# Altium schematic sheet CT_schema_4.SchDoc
size 469 x 430 mm
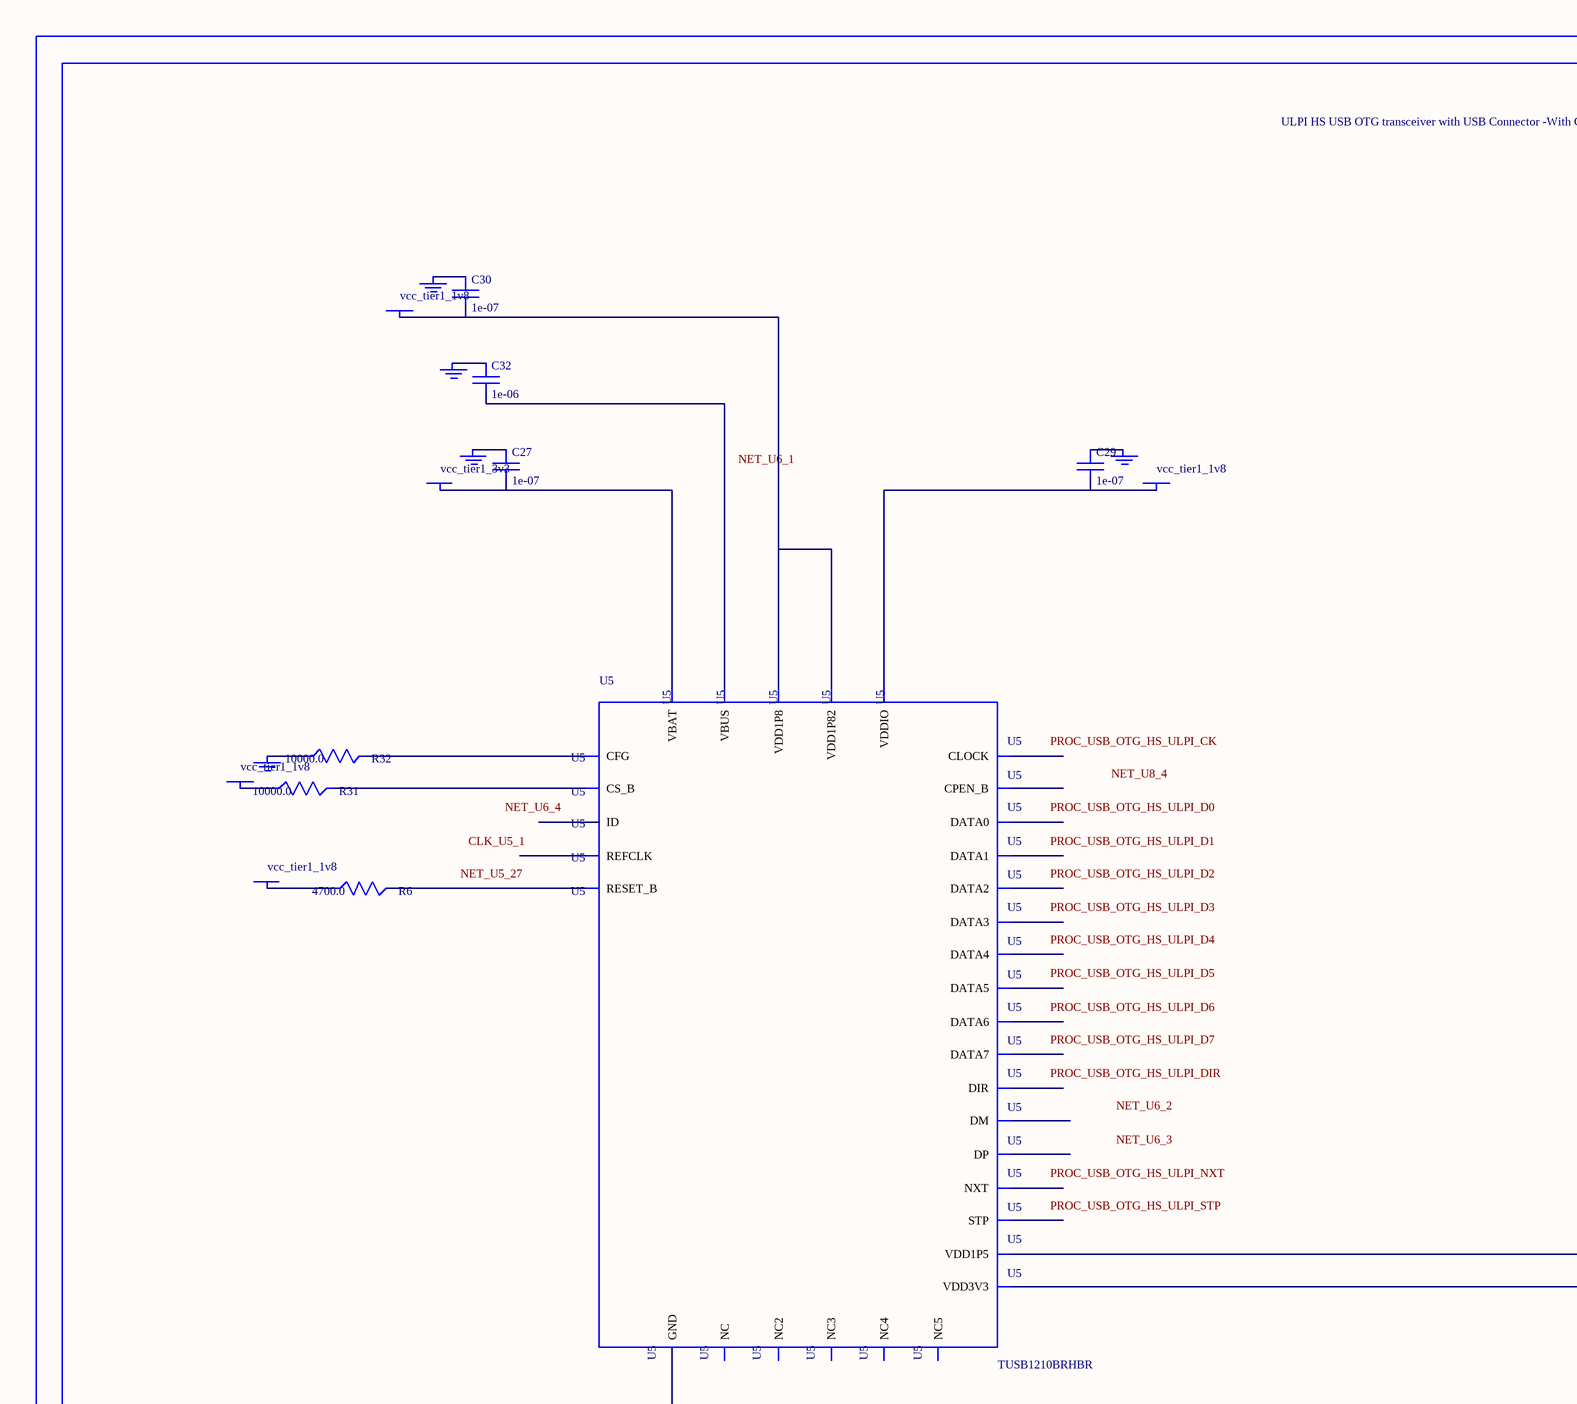
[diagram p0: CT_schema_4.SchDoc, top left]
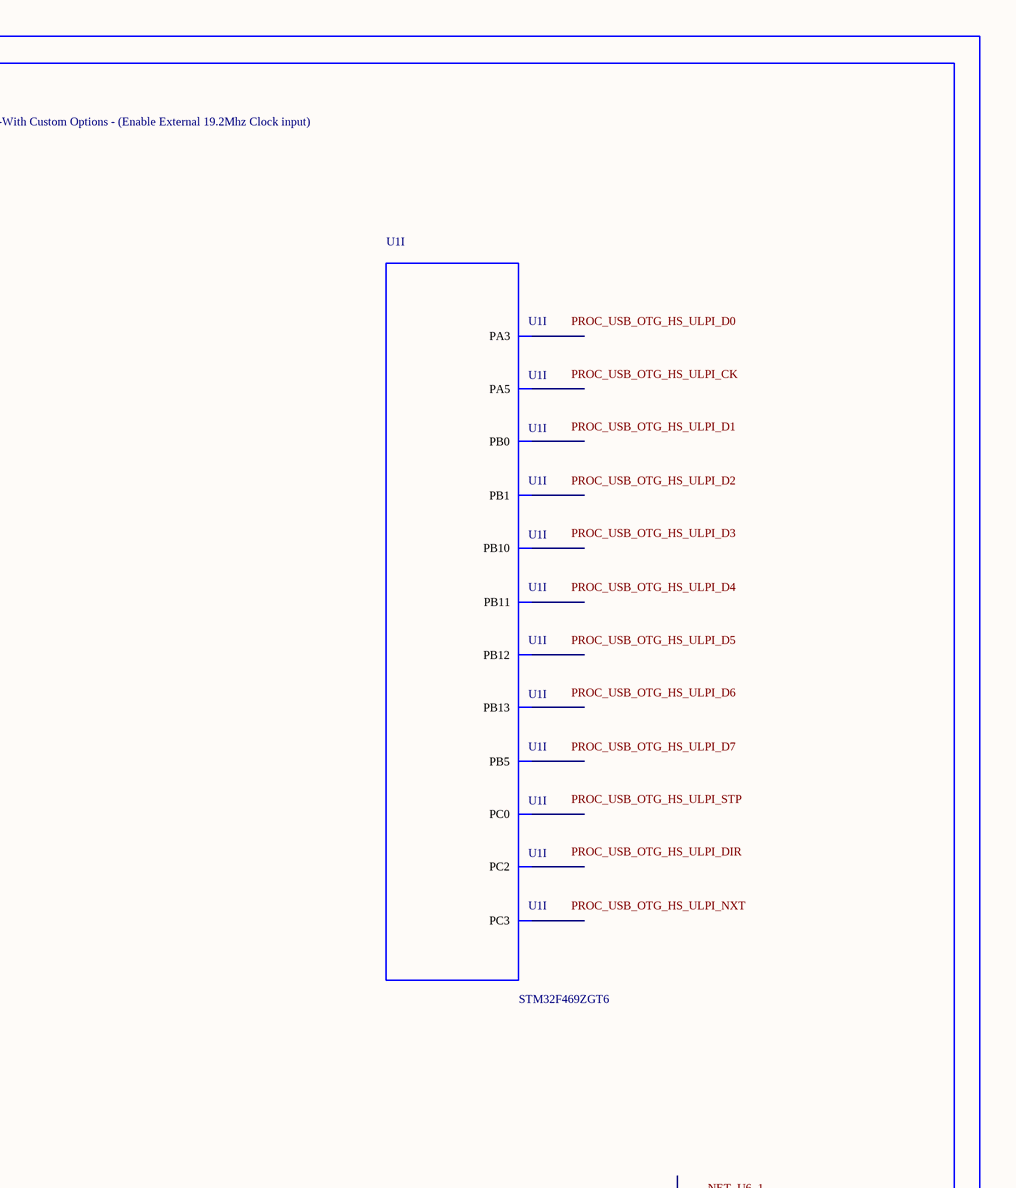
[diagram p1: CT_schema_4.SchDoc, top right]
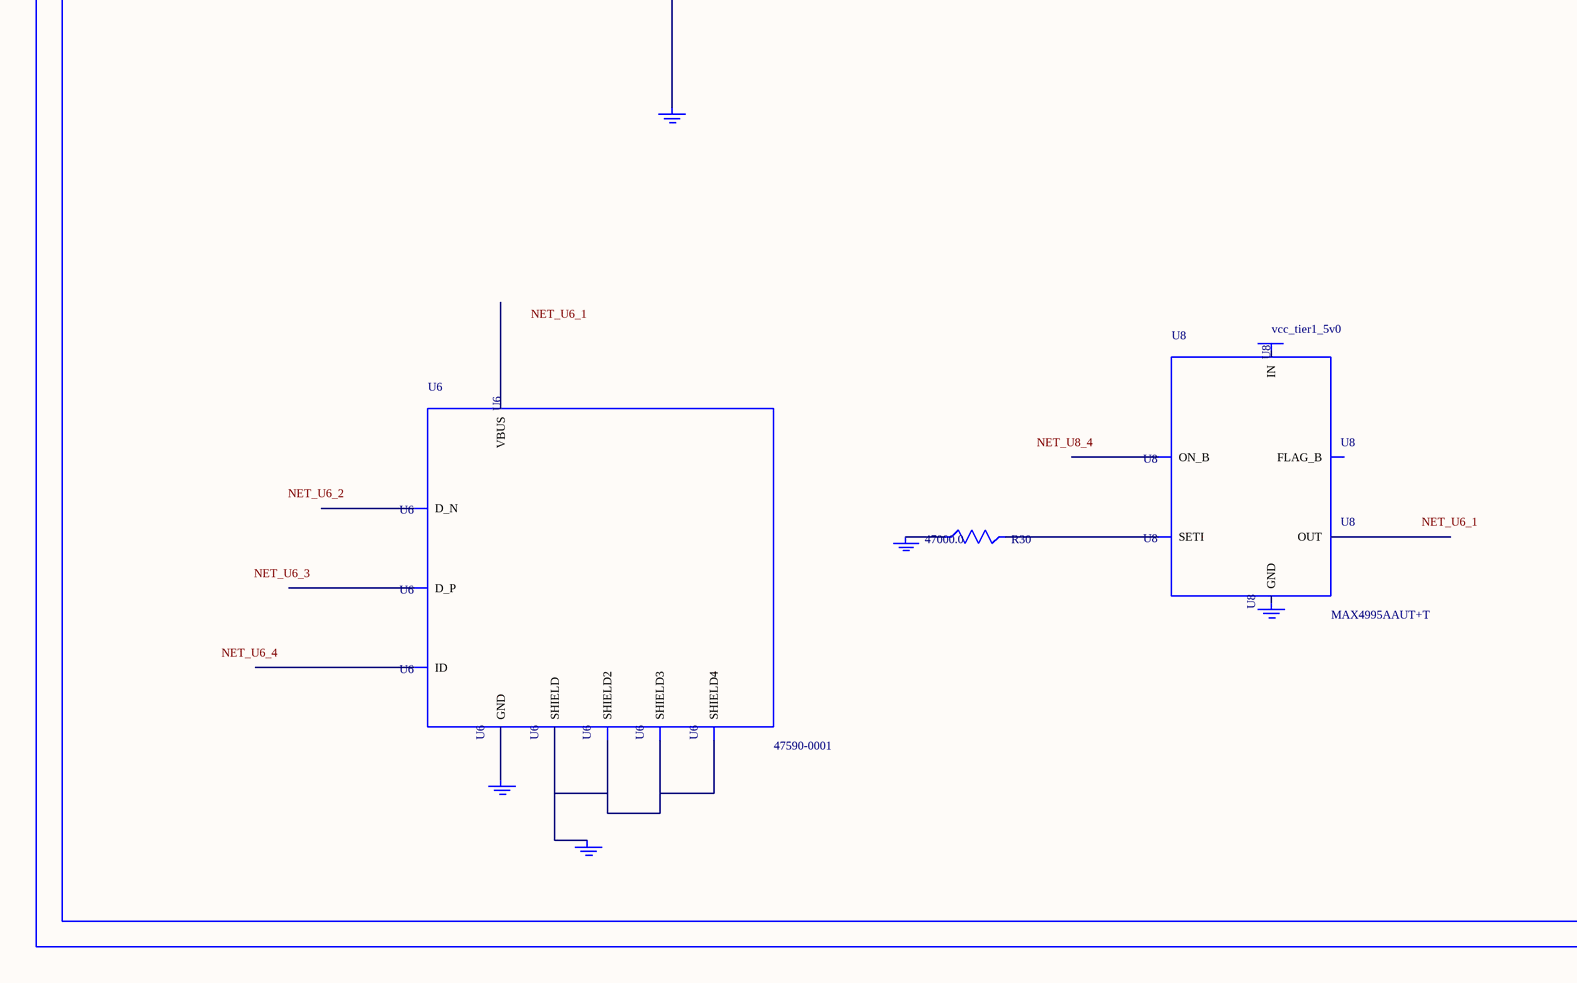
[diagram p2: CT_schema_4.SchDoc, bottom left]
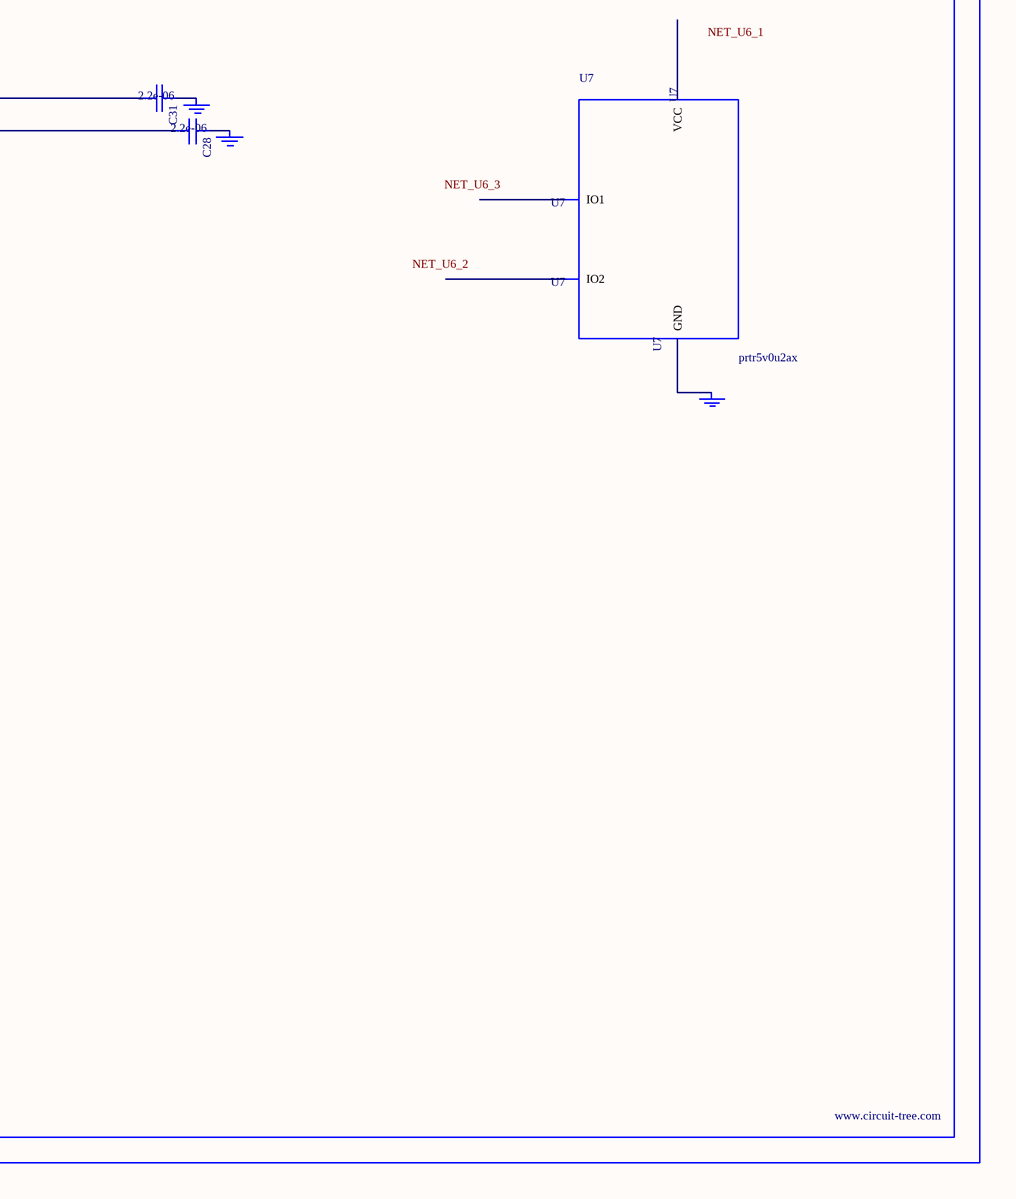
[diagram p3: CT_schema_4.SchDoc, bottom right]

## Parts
BORDER3  (no value)
C27  1e-07  [C0402]
C28  2.2e-06  [C0603]
C29  1e-07  [C0402]
C30  1e-07  [C0402]
C31  2.2e-06  [C0603]
C32  1e-06  [C0603]
GND_INSTANCE_3_0  (no value)
GND_INSTANCE_3_1  (no value)
GND_INSTANCE_3_2  (no value)
GND_INSTANCE_3_3  (no value)
GND_INSTANCE_3_4  (no value)
GND_INSTANCE_3_5  (no value)
GND_INSTANCE_3_6  (no value)
GND_INSTANCE_3_7  (no value)
GND_INSTANCE_3_8  (no value)
GND_INSTANCE_3_9  (no value)
GND_INSTANCE_3_10  (no value)
GND_INSTANCE_3_11  (no value)
GND_INSTANCE_3_12  (no value)
POWER_INSTANCE_3_0  vcc_tier1_1v8
POWER_INSTANCE_3_1  vcc_tier1_3v3
POWER_INSTANCE_3_2  vcc_tier1_1v8
POWER_INSTANCE_3_3  vcc_tier1_1v8
POWER_INSTANCE_3_4  vcc_tier1_1v8
POWER_INSTANCE_3_5  vcc_tier1_5v0
R6  4700.0  [R0603]
R30  47000.0  [R0603]
R31  10000.0  [R0603]
R32  10000.0  [R0603]
U1  STM32F469ZGT6  [LQFP144]  (part I of 12)
U5  TUSB1210BRHBR  [RHB32_3P45X3P45]
U6  47590-0001  [MICRO_USB_AB]
U7  prtr5v0u2ax  [SOT143B]
U8  MAX4995AAUT+T  [SOT-23-6]

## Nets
NetC27_1: C27.1 GND_INSTANCE_3_3.0(GND)
NetC27_2: C27.2 POWER_INSTANCE_3_1.0(PWR) U5.21(VBAT)
NetC28_1: C28.1 GND_INSTANCE_3_2.0(GND)
NetC28_2: C28.2 U5.20(VDD3V3)
NetC29_1: C29.1 GND_INSTANCE_3_6.0(GND)
NetC29_2: C29.2 POWER_INSTANCE_3_3.0(PWR) U5.32(VDDIO)
NetC30_1: C30.1 GND_INSTANCE_3_5.0(GND)
NetC30_2: C30.2 POWER_INSTANCE_3_2.0(PWR) U5.28(VDD1P8) U5.30(VDD1P82)
NetC31_1: C31.1 GND_INSTANCE_3_0.0(GND)
NetC31_2: C31.2 U5.12(VDD1P5)
NetC32_1: C32.1 GND_INSTANCE_3_4.0(GND)
NetC32_2: C32.2 U5.22(VBUS)
NetGND_INSTANCE_3_1_0: GND_INSTANCE_3_1.0(GND) R32.1
NetGND_INSTANCE_3_7_0: GND_INSTANCE_3_7.0(GND) U5.33(GND)
NetGND_INSTANCE_3_8_0: GND_INSTANCE_3_8.0(GND) U6.6(SHIELD) U6.7(SHIELD2) U6.8(SHIELD3) U6.9(SHIELD4)
NetGND_INSTANCE_3_9_0: GND_INSTANCE_3_9.0(GND) U6.5(GND)
NetGND_INSTANCE_3_10_0: GND_INSTANCE_3_10.0(GND) U7.1(GND)
NetGND_INSTANCE_3_11_0: GND_INSTANCE_3_11.0(GND) R30.1
NetPOWER_INSTANCE_3_0_0: POWER_INSTANCE_3_0.0(PWR) R31.1
NetPOWER_INSTANCE_3_4_0: POWER_INSTANCE_3_4.0(PWR) R6.1
NetR6_2: R6.2 U5.27(RESET_B)
NetR30_2: R30.2 U8.3(SETI)
NetR31_2: R31.2 U5.11(CS_B)
NetR32_2: R32.2 U5.14(CFG)

Not connected (* = marked no-connect by the designer): GND_INSTANCE_3_12 0(GND); POWER_INSTANCE_3_5 0(PWR); U1 21(PC0) 23(PC2) 24(PC3) 32(PA3) 36(PA5) 41(PB0) 42(PB1) 63(PB10) 64(PB11) 67(PB12) 68(PB13) 134(PB5); U5 1(REFCLK) 2(NXT) 3(DATA0) 4(DATA1) 5(DATA2) 6(DATA3) 7(DATA4) 8(NC) 9(DATA5) 10(DATA6) 13(DATA7) 15(NC2) 16(NC3) 17(CPEN_B) 18(DP) 19(DM) 23(ID) 24(NC4) 25(NC5) 26(CLOCK) 29(STP) 31(DIR); U6 1(VBUS) 2(D_N) 3(D_P) 4(ID); U7 2(IO1) 3(IO2) 4(VCC); U8 1(OUT) 2(GND) 4(ON_B) 5(IN) 6(FLAG_B)

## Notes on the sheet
- Labels drawn without touching a wire or pin: CLK_U5_1, NET_U5_27, NET_U6_1, NET_U6_2, NET_U6_3, NET_U6_4, NET_U8_4, PROC_USB_OTG_HS_ULPI_CK, PROC_USB_OTG_HS_ULPI_D0, PROC_USB_OTG_HS_ULPI_D1, PROC_USB_OTG_HS_ULPI_D2, PROC_USB_OTG_HS_ULPI_D3, PROC_USB_OTG_HS_ULPI_D4, PROC_USB_OTG_HS_ULPI_D5, PROC_USB_OTG_HS_ULPI_D6, PROC_USB_OTG_HS_ULPI_D7, PROC_USB_OTG_HS_ULPI_DIR, PROC_USB_OTG_HS_ULPI_NXT, PROC_USB_OTG_HS_ULPI_STP

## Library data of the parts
BORDER3 = BORDER_PAGE3
C27 C29 C30 = C0402C104K3RACTU
C28 C31 = C0603C225K8RACTU
C32 = C0603C105K3RACTU
GND_INSTANCE_3_0-GND_INSTANCE_3_12 = GND
POWER_INSTANCE_3_0-POWER_INSTANCE_3_5 = PWR
R6 = RC0603JR-074K7L
R30 = RC0603JR-0747KL
R31 R32 = RC0603JR-0710KL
